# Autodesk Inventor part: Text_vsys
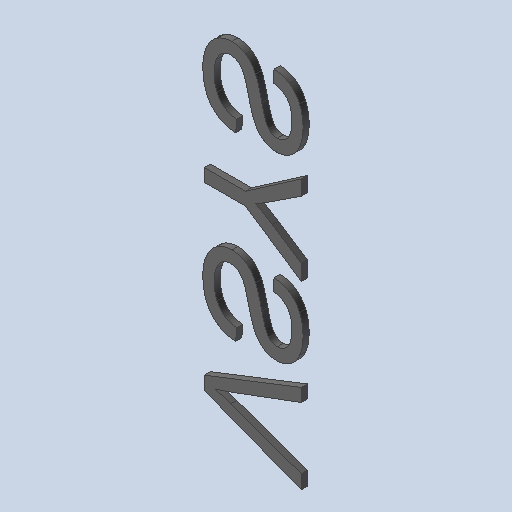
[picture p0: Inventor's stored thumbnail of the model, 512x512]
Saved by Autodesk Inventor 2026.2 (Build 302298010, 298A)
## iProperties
Created: 2026-10
Part Number: Text_vsys
Material: Générique
Document SubType Name: Modeling
Designer: mel
Density: 1 g/cm^3
Appearance: Par défaut
Author: mel
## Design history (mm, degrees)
feature "Base1"
feature "Base2"
feature "Base3"
feature "Base4"
node "Solide1"
node "Solide2"
node "Solide3"
node "Solide4"
